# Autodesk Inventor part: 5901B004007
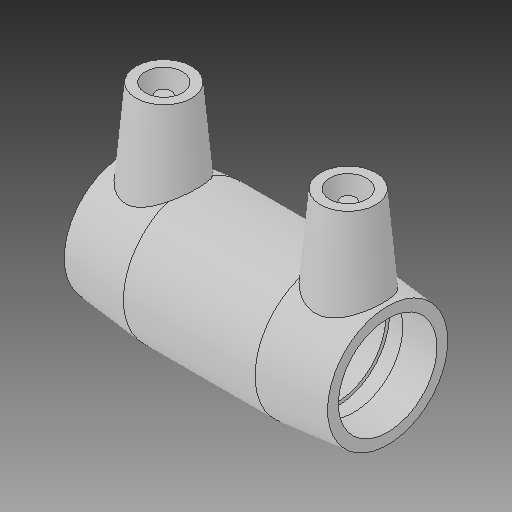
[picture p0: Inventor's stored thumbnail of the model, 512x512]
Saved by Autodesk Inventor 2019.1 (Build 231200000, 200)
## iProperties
Created: 2017-06
Part Number: 5901B004007
Material: Generic
Description: PLASSON IPS COUPLER 3/4''
Document SubType Name: Modeling
Designer: KIM
Mass: 8622.19 g
Surface Area: 6772.47 cm^2
Volume: 8622.19 cm^3
Density: 1 g/cm^3
Appearance: Default
Author: KIM
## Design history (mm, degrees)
derived "5901B.ipt"
feature "Solid1::5901B.ipt"
tag "TaggingFeature1"
body "Solid1"
other parameters: "d0" = 71.12, "d1" = 26.6, "d2" = 36.068, "d3" = 34.544, "d4" = 17.78, "d5" = 32.4612, "d6" = 21.28, "d7" = 26.6, "d8" = 168 deg, "d10" = 13.8176, "d11" = 4.60587, "d13" = 71.12, "d14" = 17.6296, "d18" = 26.6, "d19" = 3.52592, "d20" = 168 deg, "d22" = 33.90392, "d23" = 36.068, "d24" = 32.8868, "d25" = 135 deg, "d26" = 32.004, "d27" = 135 deg, "d29" = 38.354, "d30" = 15, "d31" = 24.892, "d34" = 5 deg, "d35" = 15, "d39" = 5 deg, "d41" = 4, "d42" = 14, "d43" = 0, "d45" = 4, "d46" = 14, "d47" = 0, "d48" = 3, "d49" = 0, "d50" = 3, "d51" = 0, "d52" = 10.01776, "d53" = 2.50444, "d55" = 34.544, "d_" = 26.6, "L_" = 71.12, "L_1" = 34.544, "D_" = 36.068, "A_" = 38.354, "d_2" = 12, "B_" = 38.354
